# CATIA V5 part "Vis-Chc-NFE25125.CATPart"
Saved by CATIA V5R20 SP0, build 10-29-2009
Part number: Vis-Chc-M10x20
Bounding box of the stored display mesh (mm): x -7.954 to 7.954, y -7.954 to 7.954, z -20 to 10
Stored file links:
  C:\travail\CATIA\visserie\Vis-Chc-NFE25125.CATPart
  C:\travail\CATIA\visserie\vis-Chc-NFE25125.xls
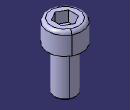
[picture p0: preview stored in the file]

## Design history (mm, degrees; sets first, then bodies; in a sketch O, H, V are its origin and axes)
External parameters (linked from other documents)
  External.Dn = 10 mm {design table}
  External.Dk = 16 mm {design table}
  External.K = 10 mm {design table}
  External.Pas = 1.5 mm {design table}
  External.Norme = "NF E25.125" {design table}
  External.S = 8 mm {design table}
  External.T = 5 mm {design table}
  External.Nom = "Vis-Chc-M10x20" {design table}
  External.I = 20 mm {design table}
  External.FILETAGE = "M10" {design table}
Body1 (main body)
  Sketch1 on yz-plane, origin (0, 0, 0), H (0, 1, 0), V (0, 0, 1)
    axis line L1 (0, 67.3524) -> (0, -76.5862)
    point P1 (0, 67.3524)
    point P3 (0, 10)
    line L2 (0, 10) -> (8, 10)
    line L3 (8, 10) -> (8, 0)
    point P5 (8, 0)
    line L4 (8, 0) -> (6.5, 0)
    line L5 (5, -1.5) -> (5, -20)
    line L6 (5, -20) -> (0, -20)
    point P7 (0, -20)
    arc A1 centre (6.5, -1.5) radius 1.5 from (6.5, 0) to (5, -1.5) ccw
    "Radius" L1 L5 = 5 {= External.Dn /2}
    radius A1 = 1.5 {= External.Pas}
    "Radius" L3 L1 = 8 {= External.Dk /2}
    distance L2 L4 = 10 {= External.K}
    distance L4 L6 = 20 {= External.I}
    coincidence: P1 V, P3 L1, P5 H, P7 V
    vertical: L1 V, L3 V, L5 V
    horizontal: L2 H, L4 H, L6 H
    tangency: A1 L4, A1 L5
  Shaft1: profile Sketch1, axis Sketch1.L1, angle 360
  Fillet1: radius 1.5 {= External.Pas}, on face of Shaft1 from Sketch1.L2
  Chamfer1: length 0.75 {= External.Pas /2}, angle 45, on edge [face of Shaft1 from Sketch1.L5 | face of Shaft1 from Sketch1.L6]
  Sketch2 on face of Shaft1 from Sketch1.L2, origin (0, 0, 10), H (1, 0, 0), V (0, 1, 0)
    construction circle A1 centre (0, 0) radius 4.6188
    point P1 (0, 4.6188)
    line L1 (0, 4.6188) -> (-4, 2.3094)
    point P2 (-4, 2.3094)
    line L2 (-4, 2.3094) -> (-4, -2.3094)
    point P3 (-4, -2.3094)
    line L3 (-4, -2.3094) -> (0, -4.6188)
    point P4 (0, -4.6188)
    line L4 (0, -4.6188) -> (4, -2.3094)
    point P5 (4, -2.3094)
    line L5 (4, -2.3094) -> (4, 2.3094)
    point P6 (4, 2.3094)
    line L6 (4, 2.3094) -> (0, 4.6188)
    distance L6 L3 = 8 {= Sketch2.distance(L5 L2)}
    distance L5 L2 = 8 {= External.S}
    coincidence: P1 A1, P1 V, P2 A1, P3 A1, P4 A1, P4 V, P5 A1, P6 A1
    vertical: L2 V, L5 V
    parallelism: L4 L1
  Pocket1: profile Sketch2, direction (0, 0, -1), length 5 {= External.T}
  Thread1: "M10", diameter 10, depth 17 {= External.I - (2*External.Pas )}, pitch 1.5, on face of Shaft1 from Sketch1.L5, from face of Shaft1 from Sketch1.L6
Relations
  design table, configuration 30, drives External.Dn, External.I, External.K, External.Dk, External.S, External.T, External.Nom, External.Norme, External.Pas, External.FILETAGE
  Thread1.ThreadDescription = External.FILETAGE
